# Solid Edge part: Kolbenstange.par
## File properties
Username: ahadarics
Dokumentum tartalom típus: 0
Author: ahadarics
Last saved by: ahadarics
Revision: 87
Sűrűség: 0,000 kg/m^3
Pontosság: 0,990
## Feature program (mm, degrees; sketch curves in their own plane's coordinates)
base feature "unnamed BaseFeature 1"
thread "unnamed Thread 1"
chamfer "Letörés_1" setback 0.7
sketch for "Kihúzás_1" plane through (57.5, 0, 0) normal (1, 0, 0) x-axis (0, 1, 0)
  circle centre (0, 0) radius 12.5
extrude "Kihúzás_1" add finite 27 along -normal
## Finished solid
Body 1: solid body, 13 faces, 23 edges, 12 vertices.
  Faces by surface: plane 9, cylinder 3, cone 1
  Edges by curve: line 12, circle 11
Bounding box of the edges (mm): 594.500 x 25.000 x 25.000, from (-537, -12.5, -12.5) to (57.5, 12.5, 12.5).
Cylindrical faces by radius (mm): R5 x2, R12.5 x1
Conical faces (half-angle, radius in mm at the cone's reference point): 45 deg R4.3 x1
Planar faces by outward normal: +x 3, +z 1, -x 4, -z 1
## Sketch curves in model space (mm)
circle centre (57.5, 0, 0) radius 12.5
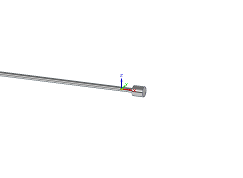
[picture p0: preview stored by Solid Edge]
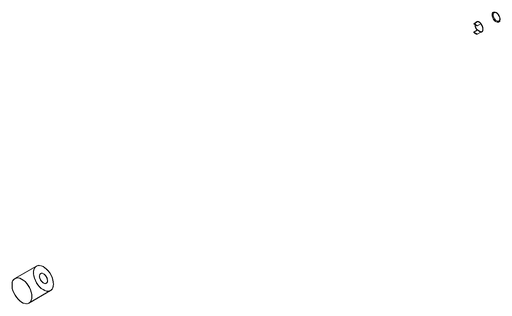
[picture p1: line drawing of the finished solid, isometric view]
